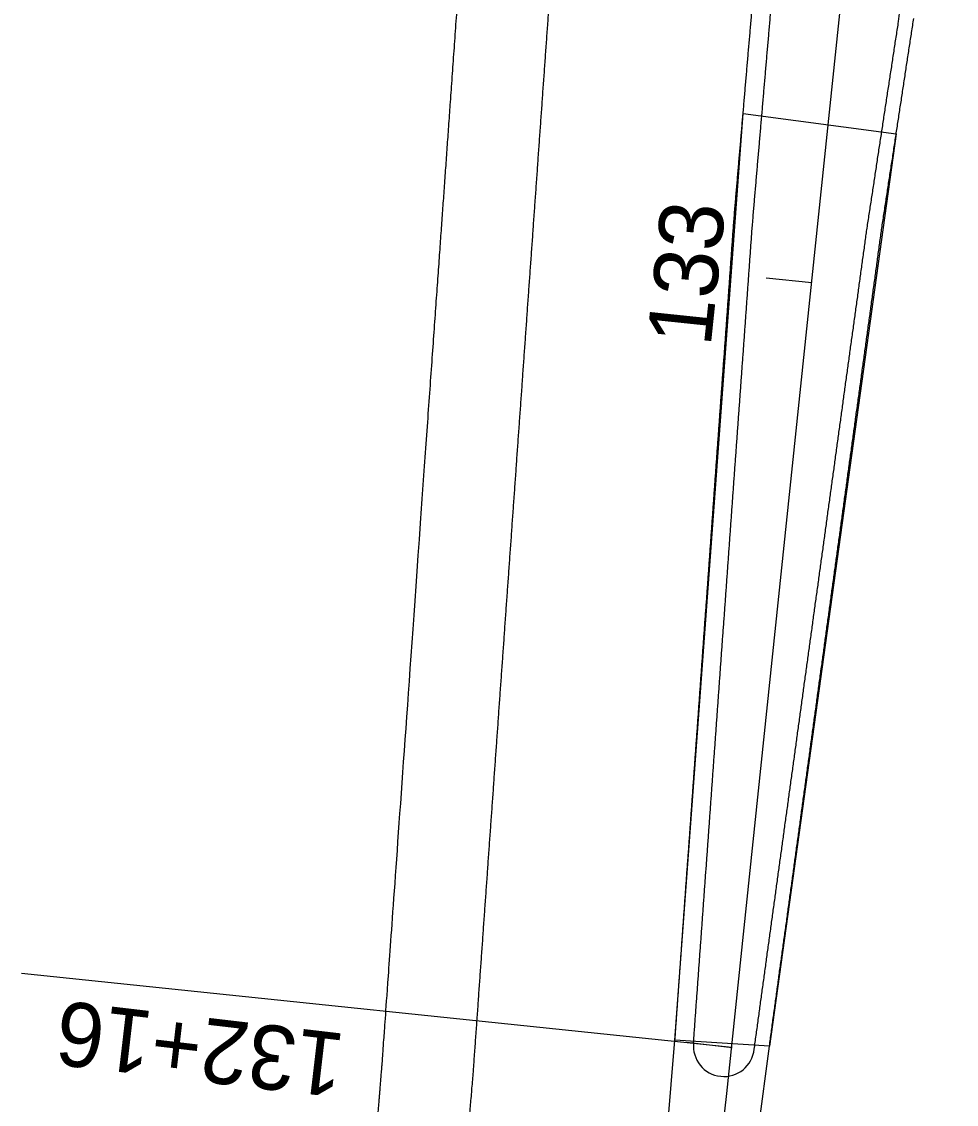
# Model space of a CAD drawing. Extents: x 2318076 to 2324211, y 613525 to 630327.
# Drawn here: x 2320454.8 to 2320556.9, y 627782.7 to 627901 of the extents above; entities that cross this region are included whole.
import ezdxf

# ---------------------------------------------------------------- set-up
doc = ezdxf.new("R2010")
doc.units = 0
for name, color, linetype in [('GE_P_CL_50', 7, 'Continuous'), ('PM_P_CL_Double_Solid', 7, 'Continuous'), ('PM_P_Island', 7, 'Continuous'), ('PV_P_EOP', 7, 'Continuous'), ('PV_P_Shoulder', 7, 'Continuous'), ('PV_X_Curb', 7, 'Continuous')]:
    doc.layers.add(name, color=color, linetype=linetype)

msp = doc.modelspace()

# ---------------------------------------------------------------- linework, layer by layer
at = {"layer": 'GE_P_CL_50'}
for p, q in [((2320541.08, 627872.43), (2320536.11, 627872.95)), ((2320532.34, 627788.89), (2320454.76, 627797)), ((2320532.4, 627788.88), (2320527.44, 627789.46))]:
    msp.add_line(p, q, dxfattribs=at)
msp.add_lwpolyline([(2320476.3, 627307.7), (2320485.22, 627375.57), (2320502.11, 627520.92), (2320519.22, 627676.47), (2320531.82, 627783.89), (2320546.8, 627927.12), (2320554.45, 627991.34), (2320572.51, 628138.41), (2320649.52, 628804.84), (2320678.77, 629064.5), (2320690.76, 629163.78), (2320713.75, 629362.45), (2320725.26, 629461.78), (2320736.97, 629561.09), (2320748.4, 629660.43), (2320759.09, 629759.86), (2320769.62, 629859.3), (2320777.51, 629931.12), (2320778.25, 629937.84)], dxfattribs=at)
at = {"layer": 'PM_P_CL_Double_Solid'}
for q in [(2320526.13, 627789.71), (2320536.46, 627789.06)]:
    msp.add_line((2320507.98, 627574.27), q, dxfattribs=at)
at = {"layer": 'PM_P_Island'}
msp.add_lwpolyline([(2320536.46, 627789.06), (2320526.13, 627789.71), (2320533.58, 627890.94), (2320550.3, 627888.71)], close=True, dxfattribs=at)
at = {"layer": 'PV_P_EOP'}
for points in [[(2320508.32, 627845.49), (2320508.38, 627846.39), (2320508.45, 627847.29), (2320508.51, 627848.19), (2320508.58, 627849.08), (2320508.64, 627849.98), (2320508.7, 627850.88), (2320508.77, 627851.78), (2320508.83, 627852.68), (2320508.89, 627853.58), (2320508.96, 627854.48), (2320509.02, 627855.38), (2320509.09, 627856.28), (2320509.15, 627857.18), (2320509.21, 627858.08), (2320509.28, 627858.98), (2320509.34, 627859.87), (2320509.41, 627860.77), (2320509.47, 627861.67), (2320509.53, 627862.57), (2320509.6, 627863.47), (2320509.66, 627864.37), (2320509.72, 627865.27), (2320509.79, 627866.17), (2320509.85, 627867.07), (2320509.92, 627867.97), (2320509.98, 627868.87), (2320510.04, 627869.76), (2320510.11, 627870.66), (2320510.17, 627871.56), (2320510.24, 627872.46), (2320510.3, 627873.36), (2320510.36, 627874.26), (2320510.43, 627875.16), (2320510.49, 627876.06), (2320510.56, 627876.96), (2320510.62, 627877.86), (2320510.68, 627878.76), (2320510.75, 627879.66), (2320510.81, 627880.55), (2320510.87, 627881.45), (2320510.94, 627882.35), (2320511, 627883.25), (2320511.07, 627884.15), (2320511.13, 627885.05), (2320511.19, 627885.95), (2320511.26, 627886.85), (2320511.32, 627887.75), (2320511.39, 627888.65), (2320511.45, 627889.55), (2320511.51, 627890.45), (2320511.58, 627891.34), (2320511.64, 627892.24), (2320511.7, 627893.14), (2320511.77, 627894.04), (2320511.83, 627894.94), (2320511.9, 627895.84), (2320511.96, 627896.74), (2320512.02, 627897.64), (2320512.09, 627898.54), (2320512.15, 627899.44), (2320512.22, 627900.34), (2320512.28, 627901.23), (2320512.34, 627902.13), (2320512.41, 627903.03), (2320512.47, 627903.93), (2320512.53, 627904.83), (2320512.6, 627905.73), (2320512.66, 627906.63), (2320512.73, 627907.53), (2320512.79, 627908.43), (2320512.85, 627909.33), (2320512.92, 627910.23), (2320513.05, 627912.02)], [(2320530.2, 627846.28), (2320530.26, 627847.05), (2320530.31, 627847.81), (2320530.37, 627848.58), (2320530.42, 627849.34), (2320530.48, 627850.11), (2320530.53, 627850.87), (2320530.59, 627851.63), (2320530.64, 627852.4), (2320530.7, 627853.16), (2320530.75, 627853.93), (2320530.81, 627854.69), (2320530.86, 627855.46), (2320530.92, 627856.22), (2320530.97, 627856.99), (2320531.03, 627857.75), (2320531.08, 627858.51), (2320531.14, 627859.28), (2320531.19, 627860.04), (2320531.25, 627860.81), (2320531.3, 627861.57), (2320531.36, 627862.34), (2320531.41, 627863.1), (2320531.47, 627863.87), (2320531.53, 627864.63), (2320531.58, 627865.4), (2320531.64, 627866.16), (2320531.69, 627866.92), (2320531.75, 627867.69), (2320531.8, 627868.45), (2320531.86, 627869.22), (2320531.91, 627869.98), (2320531.97, 627870.75), (2320532.02, 627871.51), (2320532.08, 627872.28), (2320532.13, 627873.04), (2320532.19, 627873.8), (2320532.24, 627874.57), (2320532.3, 627875.33), (2320532.35, 627876.1), (2320532.41, 627876.86), (2320532.46, 627877.63), (2320532.52, 627878.39), (2320532.57, 627879.16), (2320532.64, 627880.01), (2320532.7, 627880.77), (2320532.77, 627881.54), (2320532.83, 627882.3), (2320532.9, 627883.06), (2320532.97, 627883.83), (2320533.03, 627884.59), (2320533.1, 627885.36), (2320533.16, 627886.12), (2320533.23, 627886.88), (2320533.3, 627887.65), (2320533.36, 627888.41), (2320533.43, 627889.17), (2320533.49, 627889.94), (2320533.56, 627890.7), (2320533.63, 627891.46), (2320533.69, 627892.23), (2320533.76, 627892.99), (2320533.82, 627893.76), (2320533.89, 627894.52), (2320533.96, 627895.28), (2320534.02, 627896.05), (2320534.09, 627896.81), (2320534.15, 627897.57), (2320534.22, 627898.34), (2320534.29, 627899.1), (2320534.35, 627899.86), (2320534.42, 627900.63), (2320534.48, 627901.39), (2320534.62, 627902.92)], [(2320544.18, 627845.25), (2320544.28, 627846.01), (2320544.39, 627846.77), (2320544.49, 627847.53), (2320544.6, 627848.29), (2320544.7, 627849.05), (2320544.81, 627849.81), (2320544.91, 627850.57), (2320545.01, 627851.33), (2320545.12, 627852.09), (2320545.22, 627852.85), (2320545.33, 627853.61), (2320545.43, 627854.37), (2320545.54, 627855.13), (2320545.64, 627855.89), (2320545.75, 627856.64), (2320545.85, 627857.4), (2320545.95, 627858.16), (2320546.06, 627858.92), (2320546.16, 627859.68), (2320546.27, 627860.44), (2320546.37, 627861.2), (2320546.48, 627861.96), (2320546.58, 627862.72), (2320546.68, 627863.48), (2320546.79, 627864.24), (2320546.89, 627865), (2320547, 627865.76), (2320547.1, 627866.52), (2320547.21, 627867.28), (2320547.31, 627868.03), (2320547.42, 627868.79), (2320547.52, 627869.55), (2320547.62, 627870.31), (2320547.73, 627871.07), (2320547.83, 627871.83), (2320547.94, 627872.59), (2320548.04, 627873.35), (2320548.15, 627874.11), (2320548.25, 627874.87), (2320548.35, 627875.63), (2320548.46, 627876.39), (2320548.56, 627877.15), (2320548.67, 627877.91), (2320548.76, 627878.58), (2320548.88, 627879.33), (2320548.99, 627880.09), (2320549.11, 627880.85), (2320549.22, 627881.61), (2320549.34, 627882.37), (2320549.45, 627883.12), (2320549.57, 627883.88), (2320549.68, 627884.64), (2320549.8, 627885.4), (2320549.92, 627886.15), (2320550.03, 627886.91), (2320550.15, 627887.67), (2320550.26, 627888.43), (2320550.38, 627889.19), (2320550.49, 627889.94), (2320550.61, 627890.7), (2320550.72, 627891.46), (2320550.84, 627892.22), (2320550.95, 627892.97), (2320551.07, 627893.73), (2320551.18, 627894.49), (2320551.3, 627895.25), (2320551.41, 627896.01), (2320551.53, 627896.76), (2320551.64, 627897.52), (2320551.76, 627898.28), (2320551.87, 627899.04), (2320551.99, 627899.79), (2320552.22, 627901.31)], [(2320503.53, 627779.3), (2320503.61, 627780.2), (2320503.68, 627781.1), (2320503.76, 627782), (2320503.83, 627782.9), (2320503.91, 627783.8), (2320503.98, 627784.69), (2320504.06, 627785.59), (2320504.13, 627786.49), (2320504.17, 627787.04), (2320504.23, 627787.94), (2320504.3, 627788.84), (2320504.36, 627789.74), (2320504.42, 627790.64), (2320504.49, 627791.54), (2320504.55, 627792.44), (2320504.62, 627793.34), (2320504.68, 627794.24), (2320504.74, 627795.14), (2320504.81, 627796.04), (2320504.87, 627796.93), (2320504.93, 627797.83), (2320505, 627798.73), (2320505.06, 627799.63), (2320505.13, 627800.53), (2320505.19, 627801.43), (2320505.25, 627802.33), (2320505.32, 627803.23), (2320505.38, 627804.13), (2320505.45, 627805.03), (2320505.51, 627805.93), (2320505.57, 627806.83), (2320505.64, 627807.72), (2320505.7, 627808.62), (2320505.76, 627809.52), (2320505.83, 627810.42), (2320505.89, 627811.32), (2320505.96, 627812.22), (2320506.02, 627813.12), (2320506.08, 627814.02), (2320506.15, 627814.92), (2320506.21, 627815.82), (2320506.28, 627816.72), (2320506.34, 627817.62), (2320506.4, 627818.51), (2320506.47, 627819.41), (2320506.53, 627820.31), (2320506.6, 627821.21), (2320506.66, 627822.11), (2320506.72, 627823.01), (2320506.79, 627823.91), (2320506.85, 627824.81), (2320506.91, 627825.71), (2320506.98, 627826.61), (2320507.04, 627827.51), (2320507.11, 627828.4), (2320507.17, 627829.3), (2320507.23, 627830.2), (2320507.3, 627831.1), (2320507.36, 627832), (2320507.43, 627832.9), (2320507.49, 627833.8), (2320507.55, 627834.7), (2320507.62, 627835.6), (2320507.68, 627836.5), (2320507.74, 627837.4), (2320507.81, 627838.3), (2320507.87, 627839.19), (2320507.94, 627840.09), (2320508, 627840.99), (2320508.06, 627841.89), (2320508.13, 627842.79), (2320508.19, 627843.69), (2320508.26, 627844.59), (2320508.32, 627845.49)], [(2320526.13, 627789.71), (2320526.19, 627790.47), (2320526.24, 627791.24), (2320526.3, 627792), (2320526.35, 627792.77), (2320526.41, 627793.53), (2320526.46, 627794.3), (2320526.52, 627795.06), (2320526.57, 627795.83), (2320526.63, 627796.59), (2320526.68, 627797.35), (2320526.74, 627798.12), (2320526.79, 627798.88), (2320526.85, 627799.65), (2320526.9, 627800.41), (2320526.96, 627801.18), (2320527.01, 627801.94), (2320527.07, 627802.71), (2320527.12, 627803.47), (2320527.18, 627804.23), (2320527.23, 627805), (2320527.29, 627805.76), (2320527.34, 627806.53), (2320527.4, 627807.29), (2320527.45, 627808.06), (2320527.51, 627808.82), (2320527.56, 627809.59), (2320527.62, 627810.35), (2320527.67, 627811.12), (2320527.73, 627811.88), (2320527.78, 627812.64), (2320527.84, 627813.41), (2320527.89, 627814.17), (2320527.95, 627814.94), (2320528, 627815.7), (2320528.06, 627816.47), (2320528.11, 627817.23), (2320528.17, 627818), (2320528.22, 627818.76), (2320528.28, 627819.52), (2320528.33, 627820.29), (2320528.39, 627821.05), (2320528.44, 627821.82), (2320528.5, 627822.58), (2320528.55, 627823.35), (2320528.61, 627824.11), (2320528.66, 627824.88), (2320528.72, 627825.64), (2320528.77, 627826.41), (2320528.83, 627827.17), (2320528.88, 627827.93), (2320528.94, 627828.7), (2320528.99, 627829.46), (2320529.05, 627830.23), (2320529.1, 627830.99), (2320529.16, 627831.76), (2320529.21, 627832.52), (2320529.27, 627833.29), (2320529.32, 627834.05), (2320529.38, 627834.81), (2320529.43, 627835.58), (2320529.49, 627836.34), (2320529.54, 627837.11), (2320529.6, 627837.87), (2320529.65, 627838.64), (2320529.71, 627839.4), (2320529.76, 627840.17), (2320529.82, 627840.93), (2320529.87, 627841.7), (2320529.93, 627842.46), (2320529.98, 627843.22), (2320530.04, 627843.99), (2320530.09, 627844.75), (2320530.15, 627845.52), (2320530.2, 627846.28)], [(2320536.46, 627789.06), (2320536.56, 627789.82), (2320536.67, 627790.58), (2320536.77, 627791.34), (2320536.87, 627792.1), (2320536.98, 627792.86), (2320537.08, 627793.62), (2320537.19, 627794.38), (2320537.29, 627795.14), (2320537.4, 627795.9), (2320537.5, 627796.66), (2320537.6, 627797.42), (2320537.71, 627798.18), (2320537.81, 627798.93), (2320537.92, 627799.69), (2320538.02, 627800.45), (2320538.13, 627801.21), (2320538.23, 627801.97), (2320538.34, 627802.73), (2320538.44, 627803.49), (2320538.54, 627804.25), (2320538.65, 627805.01), (2320538.75, 627805.77), (2320538.86, 627806.53), (2320538.96, 627807.29), (2320539.07, 627808.05), (2320539.17, 627808.81), (2320539.27, 627809.57), (2320539.38, 627810.32), (2320539.48, 627811.08), (2320539.59, 627811.84), (2320539.69, 627812.6), (2320539.8, 627813.36), (2320539.9, 627814.12), (2320540, 627814.88), (2320540.11, 627815.64), (2320540.21, 627816.4), (2320540.32, 627817.16), (2320540.42, 627817.92), (2320540.53, 627818.68), (2320540.63, 627819.44), (2320540.74, 627820.2), (2320540.84, 627820.96), (2320540.94, 627821.71), (2320541.05, 627822.47), (2320541.15, 627823.23), (2320541.26, 627823.99), (2320541.36, 627824.75), (2320541.47, 627825.51), (2320541.57, 627826.27), (2320541.67, 627827.03), (2320541.78, 627827.79), (2320541.88, 627828.55), (2320541.99, 627829.31), (2320542.09, 627830.07), (2320542.2, 627830.83), (2320542.3, 627831.59), (2320542.41, 627832.35), (2320542.51, 627833.11), (2320542.61, 627833.86), (2320542.72, 627834.62), (2320542.82, 627835.38), (2320542.93, 627836.14), (2320543.03, 627836.9), (2320543.14, 627837.66), (2320543.24, 627838.42), (2320543.34, 627839.18), (2320543.45, 627839.94), (2320543.55, 627840.7), (2320543.66, 627841.46), (2320543.76, 627842.22), (2320543.87, 627842.98), (2320543.97, 627843.74), (2320544.08, 627844.5), (2320544.18, 627845.25)]]:
    msp.add_spline(points, degree=3, dxfattribs=at)
at = {"layer": 'PV_P_Shoulder'}
for points, degree in [([(2320498.34, 627846.2), (2320499.92, 627868.38), (2320501.5, 627890.55), (2320502.42, 627903.58)], 2), ([(2320494.16, 627787.27), (2320494.17, 627787.31), (2320494.17, 627787.41), (2320494.18, 627787.61), (2320494.19, 627787.65), (2320494.19, 627787.71), (2320494.19, 627787.73), (2320494.19, 627787.74), (2320494.19, 627787.75), (2320494.19, 627787.75), (2320494.19, 627787.76), (2320494.19, 627787.77), (2320494.2, 627787.82), (2320494.21, 627788.02), (2320494.25, 627788.52), (2320494.32, 627789.59), (2320494.48, 627791.73), (2320494.78, 627796.01), (2320495.39, 627804.58), (2320496.61, 627821.72), (2320497.65, 627836.4), (2320498.34, 627846.2)], 3), ([(2320493.57, 627780.14), (2320493.77, 627782.51), (2320493.97, 627784.89), (2320494.16, 627787.27)], 2)]:
    msp.add_open_spline(points, degree=degree, dxfattribs=at)
at = {"layer": 'PV_X_Curb'}
msp.add_line((2320550.56, 627900.97), (2320555.48, 627942.32), dxfattribs=at)
for start, end in [(174.0278, 264.0278), (264.0278, 354.0278)]:
    msp.add_arc((2320531.48, 627789.07), 3.33, start, end, dxfattribs=at)
for points in [[(2320532.24, 627845.99), (2320532.3, 627846.75), (2320532.35, 627847.52), (2320532.41, 627848.28), (2320532.46, 627849.04), (2320532.52, 627849.81), (2320532.57, 627850.57), (2320532.63, 627851.34), (2320532.68, 627852.1), (2320532.74, 627852.87), (2320532.79, 627853.63), (2320532.85, 627854.4), (2320532.9, 627855.16), (2320532.96, 627855.92), (2320533.01, 627856.69), (2320533.07, 627857.45), (2320533.12, 627858.22), (2320533.18, 627858.98), (2320533.23, 627859.75), (2320533.29, 627860.51), (2320533.34, 627861.28), (2320533.4, 627862.04), (2320533.45, 627862.81), (2320533.51, 627863.57), (2320533.56, 627864.33), (2320533.62, 627865.1), (2320533.67, 627865.86), (2320533.73, 627866.63), (2320533.78, 627867.39), (2320533.84, 627868.16), (2320533.89, 627868.92), (2320533.95, 627869.69), (2320534, 627870.45), (2320534.06, 627871.21), (2320534.11, 627871.98), (2320534.17, 627872.74), (2320534.22, 627873.51), (2320534.28, 627874.27), (2320534.33, 627875.04), (2320534.39, 627875.8), (2320534.44, 627876.57), (2320534.5, 627877.33), (2320534.55, 627878.1), (2320534.61, 627878.86), (2320534.68, 627879.71), (2320534.74, 627880.48), (2320534.81, 627881.24), (2320534.87, 627882), (2320534.94, 627882.77), (2320535.01, 627883.53), (2320535.07, 627884.3), (2320535.14, 627885.06), (2320535.2, 627885.82), (2320535.27, 627886.59), (2320535.34, 627887.35), (2320535.4, 627888.11), (2320535.47, 627888.88), (2320535.53, 627889.64), (2320535.6, 627890.4), (2320535.67, 627891.17), (2320535.73, 627891.93), (2320535.8, 627892.7), (2320535.86, 627893.46), (2320535.93, 627894.22), (2320536, 627894.99), (2320536.06, 627895.75), (2320536.13, 627896.51), (2320536.19, 627897.28), (2320536.26, 627898.04), (2320536.33, 627898.8), (2320536.39, 627899.57), (2320536.46, 627900.33), (2320536.52, 627901.1), (2320536.66, 627902.62)], [(2320542.52, 627844.91), (2320542.62, 627845.67), (2320542.73, 627846.43), (2320542.83, 627847.19), (2320542.93, 627847.95), (2320543.04, 627848.71), (2320543.14, 627849.47), (2320543.25, 627850.23), (2320543.35, 627850.99), (2320543.46, 627851.75), (2320543.56, 627852.5), (2320543.66, 627853.26), (2320543.77, 627854.02), (2320543.87, 627854.78), (2320543.98, 627855.54), (2320544.08, 627856.3), (2320544.19, 627857.06), (2320544.29, 627857.82), (2320544.4, 627858.58), (2320544.5, 627859.34), (2320544.6, 627860.1), (2320544.71, 627860.86), (2320544.81, 627861.62), (2320544.92, 627862.38), (2320545.02, 627863.14), (2320545.13, 627863.89), (2320545.23, 627864.65), (2320545.33, 627865.41), (2320545.44, 627866.17), (2320545.54, 627866.93), (2320545.65, 627867.69), (2320545.75, 627868.45), (2320545.86, 627869.21), (2320545.96, 627869.97), (2320546.07, 627870.73), (2320546.17, 627871.49), (2320546.27, 627872.25), (2320546.38, 627873.01), (2320546.48, 627873.77), (2320546.59, 627874.53), (2320546.69, 627875.29), (2320546.8, 627876.04), (2320546.9, 627876.8), (2320547, 627877.56), (2320547.1, 627878.23), (2320547.21, 627878.99), (2320547.33, 627879.75), (2320547.45, 627880.51), (2320547.56, 627881.26), (2320547.68, 627882.02), (2320547.79, 627882.78), (2320547.91, 627883.54), (2320548.02, 627884.3), (2320548.14, 627885.05), (2320548.25, 627885.81), (2320548.37, 627886.57), (2320548.48, 627887.33), (2320548.6, 627888.08), (2320548.71, 627888.84), (2320548.83, 627889.6), (2320548.94, 627890.36), (2320549.06, 627891.12), (2320549.17, 627891.87), (2320549.29, 627892.63), (2320549.4, 627893.39), (2320549.52, 627894.15), (2320549.63, 627894.9), (2320549.75, 627895.66), (2320549.87, 627896.42), (2320549.98, 627897.18), (2320550.1, 627897.94), (2320550.21, 627898.69), (2320550.33, 627899.45), (2320550.56, 627900.97)], [(2320528.17, 627789.41), (2320528.22, 627790.18), (2320528.28, 627790.94), (2320528.33, 627791.71), (2320528.39, 627792.47), (2320528.44, 627793.24), (2320528.5, 627794), (2320528.55, 627794.76), (2320528.61, 627795.53), (2320528.66, 627796.29), (2320528.72, 627797.06), (2320528.77, 627797.82), (2320528.83, 627798.59), (2320528.88, 627799.35), (2320528.94, 627800.12), (2320529, 627800.88), (2320529.05, 627801.64), (2320529.11, 627802.41), (2320529.16, 627803.17), (2320529.22, 627803.94), (2320529.27, 627804.7), (2320529.33, 627805.47), (2320529.38, 627806.23), (2320529.44, 627807), (2320529.49, 627807.76), (2320529.55, 627808.53), (2320529.6, 627809.29), (2320529.66, 627810.05), (2320529.71, 627810.82), (2320529.77, 627811.58), (2320529.82, 627812.35), (2320529.88, 627813.11), (2320529.93, 627813.88), (2320529.99, 627814.64), (2320530.04, 627815.41), (2320530.1, 627816.17), (2320530.15, 627816.93), (2320530.21, 627817.7), (2320530.26, 627818.46), (2320530.32, 627819.23), (2320530.37, 627819.99), (2320530.43, 627820.76), (2320530.48, 627821.52), (2320530.54, 627822.29), (2320530.59, 627823.05), (2320530.65, 627823.82), (2320530.7, 627824.58), (2320530.76, 627825.34), (2320530.81, 627826.11), (2320530.87, 627826.87), (2320530.92, 627827.64), (2320530.98, 627828.4), (2320531.03, 627829.17), (2320531.09, 627829.93), (2320531.14, 627830.7), (2320531.2, 627831.46), (2320531.25, 627832.23), (2320531.31, 627832.99), (2320531.36, 627833.75), (2320531.42, 627834.52), (2320531.47, 627835.28), (2320531.53, 627836.05), (2320531.58, 627836.81), (2320531.64, 627837.58), (2320531.69, 627838.34), (2320531.75, 627839.11), (2320531.8, 627839.87), (2320531.86, 627840.63), (2320531.91, 627841.4), (2320531.97, 627842.16), (2320532.02, 627842.93), (2320532.08, 627843.69), (2320532.13, 627844.46), (2320532.19, 627845.22), (2320532.24, 627845.99)], [(2320534.79, 627788.72), (2320534.9, 627789.48), (2320535, 627790.24), (2320535.11, 627791), (2320535.21, 627791.76), (2320535.32, 627792.52), (2320535.42, 627793.28), (2320535.52, 627794.04), (2320535.63, 627794.79), (2320535.73, 627795.55), (2320535.84, 627796.31), (2320535.94, 627797.07), (2320536.05, 627797.83), (2320536.15, 627798.59), (2320536.25, 627799.35), (2320536.36, 627800.11), (2320536.46, 627800.87), (2320536.57, 627801.63), (2320536.67, 627802.39), (2320536.78, 627803.15), (2320536.88, 627803.91), (2320536.99, 627804.67), (2320537.09, 627805.43), (2320537.19, 627806.18), (2320537.3, 627806.94), (2320537.4, 627807.7), (2320537.51, 627808.46), (2320537.61, 627809.22), (2320537.72, 627809.98), (2320537.82, 627810.74), (2320537.92, 627811.5), (2320538.03, 627812.26), (2320538.13, 627813.02), (2320538.24, 627813.78), (2320538.34, 627814.54), (2320538.45, 627815.3), (2320538.55, 627816.06), (2320538.65, 627816.82), (2320538.76, 627817.57), (2320538.86, 627818.33), (2320538.97, 627819.09), (2320539.07, 627819.85), (2320539.18, 627820.61), (2320539.28, 627821.37), (2320539.39, 627822.13), (2320539.49, 627822.89), (2320539.59, 627823.65), (2320539.7, 627824.41), (2320539.8, 627825.17), (2320539.91, 627825.93), (2320540.01, 627826.69), (2320540.12, 627827.45), (2320540.22, 627828.21), (2320540.32, 627828.97), (2320540.43, 627829.72), (2320540.53, 627830.48), (2320540.64, 627831.24), (2320540.74, 627832), (2320540.85, 627832.76), (2320540.95, 627833.52), (2320541.06, 627834.28), (2320541.16, 627835.04), (2320541.26, 627835.8), (2320541.37, 627836.56), (2320541.47, 627837.32), (2320541.58, 627838.08), (2320541.68, 627838.84), (2320541.79, 627839.6), (2320541.89, 627840.36), (2320541.99, 627841.11), (2320542.1, 627841.87), (2320542.2, 627842.63), (2320542.31, 627843.39), (2320542.41, 627844.15), (2320542.52, 627844.91)]]:
    msp.add_spline(points, degree=3, dxfattribs=at)

# ---------------------------------------------------------------- texts
at = {"layer": 'GE_P_CL_50'}
for s, rotation, p in [('133', 84.0278, (2320530.03, 627865.36)), ('132+16', 173.3138, (2320490.3, 627790.37))]:
    msp.add_text(s, height=7, rotation=rotation, dxfattribs=at).set_placement(p)

doc.saveas('drawing.dxf')
